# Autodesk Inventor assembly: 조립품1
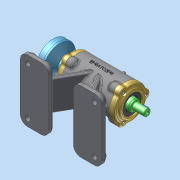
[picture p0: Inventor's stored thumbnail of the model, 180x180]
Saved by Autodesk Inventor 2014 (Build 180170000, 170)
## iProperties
Created: 2026-04
Part Number: 조립품1
Document SubType Name: Assembly
Designer: dg
Author: dg
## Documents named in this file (15)
- C:\Users\dg\Desktop\760403V1006\조립품1.iam
- C:\Users\dg\Desktop\760403V1006\부품2.ipt
- C:\Users\dg\Desktop\760403V1006\Imported Components\축\축.ipt
- C:\Users\dg\Desktop\760403V1006\Imported Components\평행 키 4x4x14\평행 키 4x4x14.ipt
- C:\Users\dg\Desktop\760403V1006\Imported Components\깊은 홈 볼 베어링 6004\깊은 홈 볼 베어링 6004.ipt
- C:\Users\dg\Desktop\760403V1006\Imported Components\커버\커버.ipt
- C:\Users\dg\Desktop\760403V1006\Imported Components\오일 실 20 35 8\오일 실 20 35 8.ipt
- C:\Users\dg\Desktop\760403V1006\Imported Components\6각 구멍붙이 볼트 M4x12\6각 구멍붙이 볼트 M4x12.ipt
- C:\Users\dg\Desktop\760403V1006\Imported Components\그리스 니플 M6x0,75\그리스 니플 M6x0,75.ipt
- C:\Users\dg\Desktop\760403V1006\Imported Components\실링\실링.ipt
- C:\Users\dg\Desktop\760403V1006\Imported Components\플러그 M6x0,75\플러그 M6x0,75.ipt
- C:\Users\dg\Desktop\760403V1006\Imported Components\플랜지\플랜지.ipt
- C:\Users\dg\Desktop\760403V1006\Imported Components\엔드 캡\엔드 캡.ipt
- C:\Users\dg\Desktop\760403V1006\Imported Components\평 와셔 M4\평 와셔 M4.ipt
- C:\Users\dg\Desktop\760403V1006\Imported Components\스프링 와셔 M4\스프링 와셔 M4.ipt
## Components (10 placed, 4 different names)
1. 6각 구멍붙이 볼트 M4x12:1
2. 6각 구멍붙이 볼트 M4x12:2
3. 6각 구멍붙이 볼트 M4x12:3
4. 6각 구멍붙이 볼트 M4x12:4
5. 6각 구멍붙이 볼트 M4x12:5
6. 6각 구멍붙이 볼트 M4x12:6
7. 그리스 니플 M6x0,75:1
8. 플러그 M6x0,75:1
9. 플랜지:1
10. 6각 구멍붙이 볼트 M4x12:7
